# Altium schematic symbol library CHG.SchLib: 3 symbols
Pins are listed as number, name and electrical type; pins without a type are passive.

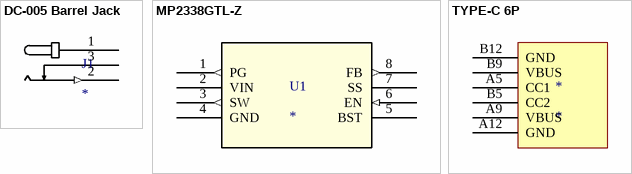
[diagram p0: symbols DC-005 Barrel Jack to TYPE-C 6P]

## DC-005 Barrel Jack
designator J1
Barrel Jack to simplify PCB complexity
pins: 1 VIN (power), 2 SW (out), 3 GND (power)

## MP2338GTL-Z
designator U1
MP2338 IC
pins: 1 PG (out), 2 VIN (power), 3 SW (out), 4 GND (power), 5 BST (power), 6 EN (in), 7 SS, 8 FB (out)

## TYPE-C 6P
designator *
pins: A5 CC1, A9 VBUS (power), A12 GND (power), B5 CC2, B9 VBUS, B12 GND (power)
